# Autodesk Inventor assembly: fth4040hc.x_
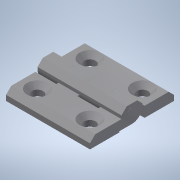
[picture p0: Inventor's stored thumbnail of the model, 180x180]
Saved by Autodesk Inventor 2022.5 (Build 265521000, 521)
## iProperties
Part Number: fth4040hc.x_
Material: 一般
Document SubType Name: Assembly
Designer: ImaoCorp
Sending System: SOLIDWORKS 2017-2017317
MC: AMD64
MC_MODEL: Intel64 Family 6 Model 60 Stepping 3, GenuineIntel
OS: Windows_NT
FRU: Parasolid Version 29.0, build 201,  4-17-2017
FORMAT: text
GUISE: transmit
KEY: fth4040hc
FILE: fth4040hc.x_t
DATE: Mon May 13 14:29:01 2019
Author: ImaoCorp
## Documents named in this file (4)
- X:\14_SW2022-Inv2022\00_全2023-1023新製品(TCC)まで\f\fth4040hc\FTH4040HC.iam
- X:\14_SW2022-Inv2022\00_全2023-1023新製品(TCC)まで\f\fth4040hc\fth4040hc_01.ipt
- X:\14_SW2022-Inv2022\00_全2023-1023新製品(TCC)まで\f\fth4040hc\fth4040hc_02.ipt
- X:\14_SW2022-Inv2022\00_全2023-1023新製品(TCC)まで\f\fth4040hc\fth4040hc_03.ipt
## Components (3 placed, 3 different names)
1. fth4040hc_01
2. fth4040hc_02
3. fth4040hc_03
